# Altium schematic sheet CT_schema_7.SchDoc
size 254 x 194 mm
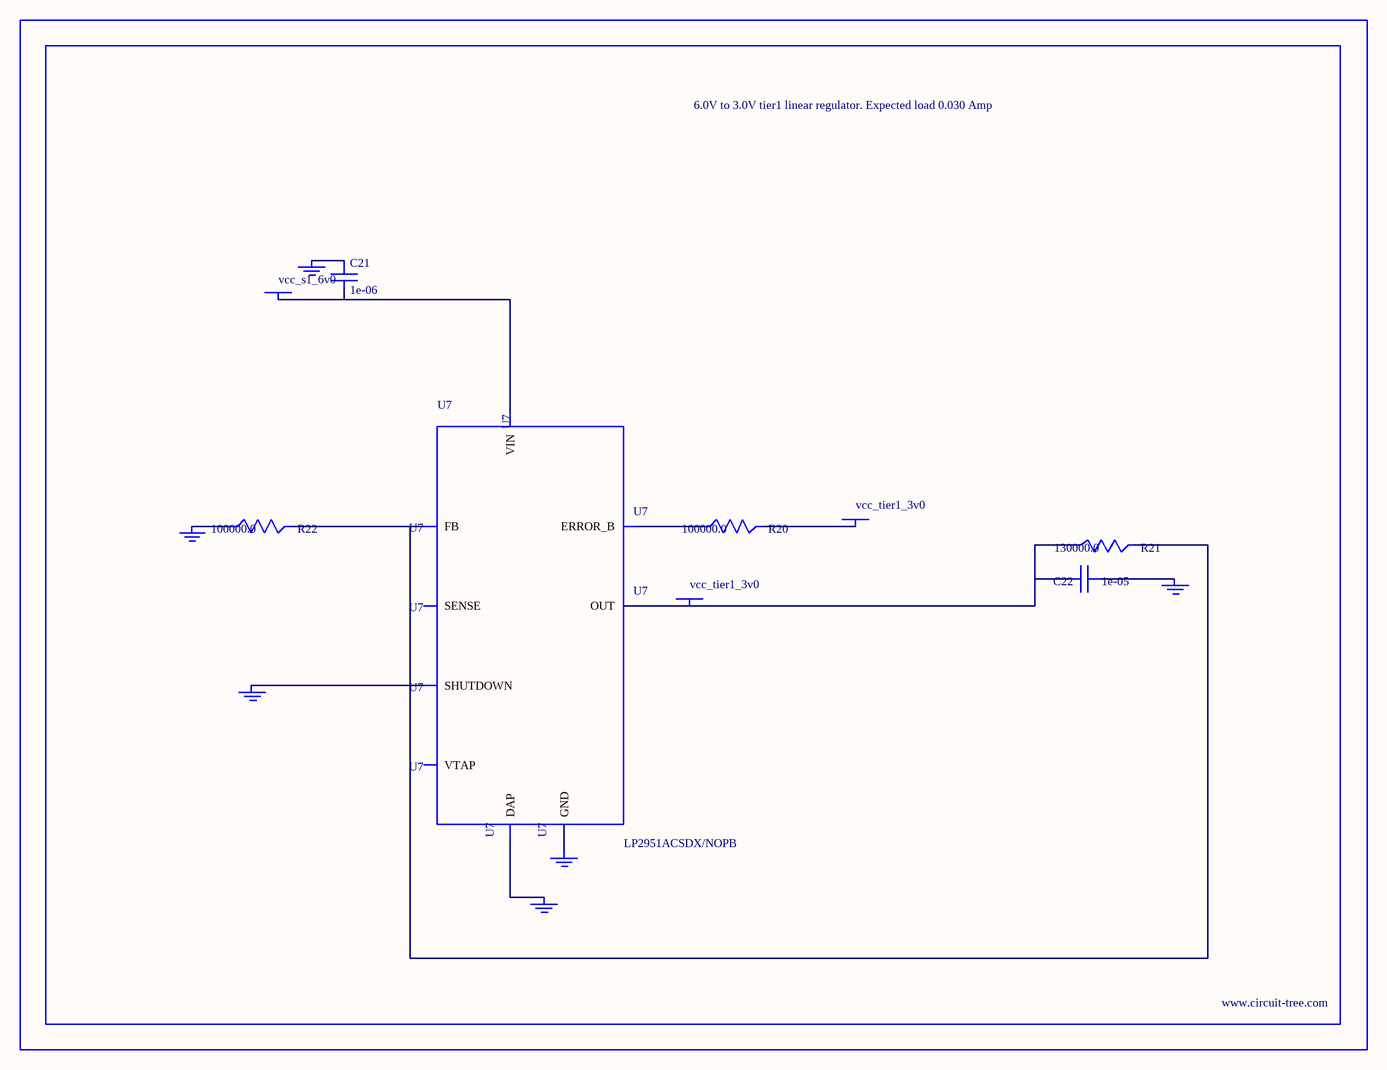
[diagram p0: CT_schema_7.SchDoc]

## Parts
BORDER6  (no value)
C21  1e-06  [C0603]
C22  1e-05  [C1210]
GND_INSTANCE_6_0  (no value)
GND_INSTANCE_6_1  (no value)
GND_INSTANCE_6_2  (no value)
GND_INSTANCE_6_3  (no value)
GND_INSTANCE_6_4  (no value)
GND_INSTANCE_6_5  (no value)
POWER_INSTANCE_6_0  vcc_tier1_3v0
POWER_INSTANCE_6_1  vcc_s1_6v0
POWER_INSTANCE_6_2  vcc_tier1_3v0
R20  100000.0  [R0603]
R21  130000.0  [R0603]
R22  100000.0  [R0603]
U7  LP2951ACSDX/NOPB  [WSON-8]

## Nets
NetC21_1: C21.1 GND_INSTANCE_6_3.0(GND)
NetC21_2: C21.2 POWER_INSTANCE_6_1.0(PWR) U7.8(VIN)
NetC22_1: C22.1 GND_INSTANCE_6_0.0(GND)
NetC22_2: C22.2 POWER_INSTANCE_6_2.0(PWR) R21.1 U7.1(OUT)
NetGND_INSTANCE_6_1_0: GND_INSTANCE_6_1.0(GND) U7.3(SHUTDOWN)
NetGND_INSTANCE_6_2_0: GND_INSTANCE_6_2.0(GND) R22.1
NetGND_INSTANCE_6_4_0: GND_INSTANCE_6_4.0(GND) U7.PAD(DAP)
NetGND_INSTANCE_6_5_0: GND_INSTANCE_6_5.0(GND) U7.4(GND)
NetPOWER_INSTANCE_6_0_0: POWER_INSTANCE_6_0.0(PWR) R20.2
NetR20_1: R20.1 U7.5(ERROR_B)
NetR21_2: R21.2 R22.2 U7.7(FB)

Not connected (* = marked no-connect by the designer): U7 2(SENSE) 6(VTAP)

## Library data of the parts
BORDER6 = BORDER_PAGE6
C21 = C0603C105K3RACTU
C22 = GRM32DR61E106MA12L
GND_INSTANCE_6_0-GND_INSTANCE_6_5 = GND
POWER_INSTANCE_6_0-POWER_INSTANCE_6_2 = PWR
R20 R22 = RC0603JR-07100KL
R21 = RC0603JR-07130KL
